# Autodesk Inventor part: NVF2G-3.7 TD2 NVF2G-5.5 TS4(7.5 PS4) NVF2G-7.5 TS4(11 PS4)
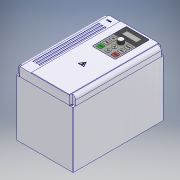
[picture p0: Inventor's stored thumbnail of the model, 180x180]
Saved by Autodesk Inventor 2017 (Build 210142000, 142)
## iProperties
Part Number: NVF2G-3.7 TD2 NVF2G-5.5 TS4(7.5 PS4) NVF2G-7.5 TS4(11 PS4)
Material: Типовые
Document SubType Name: Modeling
Designer: RSagdiev
Density: 1 g/cm^3
Appearance: По умолчанию
Mass: 6791.15 g
Surface Area: 3918.25 cm^2
Volume: 6791.15 cm^3
Author: RSagdiev
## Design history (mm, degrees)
sketch "Эскиз1"
  geometry: L1 (0, 0)-(44.679, 0) reference; L2 (0, 0)-(0, 56.035) reference; L3 (0, 0)-(247, 0); L4 (247, 0)-(247, 153.6); L5 (247, 153.6)-(0, 153.6); L6 (0, 153.6)-(0, 0)
  constraints: 12 end point, 3 horizontal, 2 parallel, 2 vertical, 1 perpendicular
  dimensions: "d0" = 247 distance of L5.end L4.end; "d1" = 153.6 distance of L4.end L3.end
extrude "Выдавливание1" new body sketch "Эскиз1" stored distance "d2" = 155; taper "d3" = 0 deg
sketch "Эскиз2"
  geometry: L1 (0, 0)-(0, 247) reference; L2 (155, 0)-(155, 247) reference; L3 (0, 247)-(10, 247); L4 (155, 247)-(155, 240); L5 (155, 0)-(145, 0); L6 (0, 0)-(0, 7); L7 (0, 247)-(155, 247) reference; L8 (0, 247)-(10, 247); L9 (10, 247)-(10, 240); L10 (10, 240)-(0, 240); L11 (0, 240)-(0, 247); L12 (155, 247)-(145, 247); L13 (145, 247)-(145, 240); L14 (145, 240)-(155, 240); L15 (155, 240)-(155, 247); L16 (0, 0)-(155, 0) reference; L17 (0, 0)-(10, 0); L18 (10, 0)-(10, 7); L19 (10, 7)-(0, 7); L20 (0, 7)-(0, 0); L21 (155, 0)-(145, 0); L22 (145, 0)-(145, 7); L23 (145, 7)-(155, 7); L24 (155, 7)-(155, 0); L25 (10, 247)-(145, 247); L26 (0, 240)-(0, 247); L27 (145, 247)-(155, 247); L28 (155, 240)-(155, 7); L29 (145, 0)-(10, 0); L30 (155, 7)-(155, 0); L31 (10, 0)-(0, 0); L32 (0, 7)-(0, 240); 1 further point
  constraints: 56 end point, 26 parallel, 13 perpendicular, 7 horizontal
  dimensions: "d4" = 10 distance of L9.end L10.end; "d5" = 7 distance of L3.end L9.end; "d6" = 10 distance of L4.end L13.end; "d7" = 7 distance of L13.end L12.end; "d8" = 10 distance of L6.end L18.end; "d9" = 7 distance of L18.end L17.end; "d10" = 10 distance of L22.end L23.end; "d11" = 7 distance of L5.end L22.end
extrude "Выдавливание2" new body sketch "Эскиз2" distance "d12" = 24; taper "d13" = 0 deg
chamfer "Фаска1" distance "d14" = 4; stored, may be unused: second distance "d15" = 2, angle "d16" = 45 deg
sketch "Эскиз3"
  geometry: L1 (10, 243)-(41.5, 243); L2 (10, 243)-(10, 240); L3 (10, 240)-(0, 240); L4 (0, 240)-(0, 7); L5 (0, 7)-(10, 7); L6 (10, 7)-(10, 0); L7 (10, 0)-(41.5, 0); L8 (145, 0)-(145, 7); L9 (145, 7)-(145, 7); L10 (145, 7)-(145, 240); L11 (145, 240)-(145, 240); L12 (145, 240)-(145, 243); L13 (10, 243)-(145, 243) reference; L14 (41.5, 243)-(41.5, 0); L15 (0, 0)-(155, 0) reference; L16 (41.5, 243)-(145, 243); L17 (41.5, 0)-(145, 0); L18 (145, 240)-(145, 243); 1 further point
  constraints: 22 end point, 2 perpendicular, 2 point on line, 1 collinear
  dimensions: "d19" = 103.5 distance between parallel lines of L14 L10
extrude "Выдавливание3" new body sketch "Эскиз3" distance "d17" = 2; taper "d18" = 0 deg
sketch "Эскиз4"
  geometry: L1 (123, 238)-(64, 238); L2 (62, 236)-(62, 147); L3 (64, 145)-(123, 145); L4 (125, 147)-(125, 236); L5 (10, 243)-(145, 243) reference; A1 r 2 centre (64, 236) between (64, 238) and (62, 236); A2 r 2 centre (123, 236) between (125, 236) and (123, 238); A3 r 2 centre (123, 147) between (123, 145) and (125, 147); A4 r 2 centre (64, 147) between (62, 147) and (64, 145); 7 further points; 1 other entity
  constraints: 8 end point, 8 point on circle, 8 tangent, 6 point on line, 4 centre point, 3 equal radius, 2 parallel, 1 horizontal, 1 perpendicular, 1 other
  dimensions: "d20" = 63 distance of point (125, 145) point (62, 145); "d21" = 93 distance of point (62, 145) point (62, 238); "d22" = 20 dimension on L4; "d23" = 5 distance between parallel lines of L5 L1; "d24" = 2 radius of A1
extrude "Выдавливание4" cut sketch "Эскиз4" distance "d25" = 0.6; taper "d26" = 0 deg
sketch "Эскиз5"
  geometry: L1 (0, 247)-(155, 247) reference; L2 (0, 0)-(0, 247) reference; L3 (155, 247)-(155, 0) reference; L4 (0, 0)-(155, 0) reference; C1 r 2.5 at (7.5, 243.5); C2 r 2.5 at (147.5, 243.5); C3 r 2.5 at (7.5, 3.5); C4 r 2.5 at (147.5, 3.5); 1 further point
  constraints: 4 centre point
  dimensions: "d27" = 5 diameter of C1; "d28" = 3.5 distance from line of C1.centre L1; "d29" = 7.5 distance from line of C1.centre L2; "d30" = 5 diameter of C2; "d31" = 3.5 distance from line of C2.centre L1; "d32" = 7.5 distance from line of C2.centre L3; "d33" = 5 diameter of C3; "d34" = 3.5 distance from line of L4 C3.centre; "d35" = 7.5 distance from line of C3.centre L2; "d36" = 5 diameter of C4; "d37" = 7.5 distance from line of C4.centre L3; "d38" = 3.5 distance from line of C4.centre L4
extrude "Выдавливание5" cut sketch "Эскиз5" stored distance "d39" = 0.6; taper "d40" = 0 deg
sketch "Эскиз6"
  geometry: L1 (62, 147)-(62, 203); L2 (123, 145)-(64, 145); L3 (125, 236)-(125, 203); L4 (64, 238)-(123, 238); L5 (62, 147)-(62, 236) reference; L6 (62, 203)-(125, 203); L7 (125, 236)-(125, 147) reference; L8 (62, 203)-(62, 236); L9 (125, 203)-(125, 147); L10 (75.5, 214)-(111.5, 214); L11 (113.5, 216)-(113.5, 226); L12 (111.5, 228)-(75.5, 228); L13 (73.5, 226)-(73.5, 216); L14 (73.5, 214)-(113.5, 228); L15 (113.5, 214)-(73.5, 228); L16 (93.5, 191.5)-(93.5, 156.857); L17 (85.25, 191.5)-(85.25, 156.857); L18 (101.75, 156.857)-(101.75, 191.5); L19 (79, 198)-(68, 198); L20 (67, 197)-(67, 186); L21 (68, 185)-(79, 185); L22 (80, 186)-(80, 197); L23 (80, 198)-(67, 185); L24 (67, 198)-(80, 185); L25 (113.5, 216)-(113.5, 217.5); L26 (73.5, 191.5)-(75.409, 191.5); L27 (26.654, 174.179)-(72.729, 174.179); L28 (26.654, 156.857)-(71.963, 156.857); L29 (120, 186)-(120, 197); L30 (108, 185)-(119, 185); L31 (120, 198)-(107, 185); L32 (107, 198)-(120, 185); L33 (107, 197)-(107, 186); L34 (119, 198)-(108, 198); L35 (120, 168.679)-(120, 179.679); L36 (108, 167.679)-(119, 167.679); L37 (120, 180.679)-(107, 167.679); L38 (107, 180.679)-(120, 167.679); L39 (107, 179.679)-(107, 168.679); L40 (119, 180.679)-(108, 180.679); L41 (120, 151.357)-(120, 162.357); L42 (108, 150.357)-(119, 150.357); L43 (120, 163.357)-(107, 150.357); L44 (107, 163.357)-(120, 150.357); L45 (107, 162.357)-(107, 151.357); L46 (119, 163.357)-(108, 163.357); L47 (80, 151.357)-(80, 162.357); L48 (68, 150.357)-(79, 150.357); L49 (80, 163.357)-(67, 150.357); L50 (67, 163.357)-(80, 150.357); L51 (67, 162.357)-(67, 151.357); L52 (79, 163.357)-(68, 163.357); L53 (80, 168.679)-(80, 179.679); L54 (68, 167.679)-(79, 167.679); L55 (80, 180.679)-(67, 167.679); L56 (67, 180.679)-(80, 167.679); L57 (67, 179.679)-(67, 168.679); L58 (79, 180.679)-(68, 180.679); L59 (123, 145)-(64, 145) reference; L60 (125, 236)-(125, 147) reference; L61 (73.5, 191.5)-(73.5, 91.5); C1 r 6.5 at (93.5, 191.5); C2 r 6.5 at (93.5, 156.857); C3 r 6.5 at (93.5, 174.179); A1 r 2 centre (75.5, 226) between (75.5, 228) and (73.5, 226); A2 r 2 centre (111.5, 226) between (113.5, 226) and (111.5, 228); A3 r 2 centre (111.5, 216) between (111.5, 214) and (113.5, 216); A4 r 2 centre (75.5, 216) between (73.5, 216) and (75.5, 214); A5 r 8.25 centre (93.5, 191.5) between (101.75, 191.5) and (85.25, 191.5); A6 r 8.25 centre (93.5, 156.857) between (85.25, 156.857) and (101.75, 156.857); A7 r 1 centre (79, 197) between (80, 197) and (79, 198); A8 r 1 centre (79, 186) between (79, 185) and (80, 186); A9 r 1 centre (68, 186) between (67, 186) and (68, 185); A10 r 1 centre (68, 197) between (68, 198) and (67, 197); A11 r 1 centre (119, 186) between (119, 185) and (120, 186); A12 r 1 centre (119, 197) between (120, 197) and (119, 198); A13 r 1 centre (108, 197) between (108, 198) and (107, 197); A14 r 1 centre (108, 186) between (107, 186) and (108, 185); A15 r 1 centre (119, 168.679) between (119, 167.679) and (120, 168.679); A16 r 1 centre (119, 179.679) between (120, 179.679) and (119, 180.679); A17 r 1 centre (108, 179.679) between (108, 180.679) and (107, 179.679); A18 r 1 centre (108, 168.679) between (107, 168.679) and (108, 167.679); A19 r 1 centre (119, 151.357) between (119, 150.357) and (120, 151.357); A20 r 1 centre (119, 162.357) between (120, 162.357) and (119, 163.357); A21 r 1 centre (108, 162.357) between (108, 163.357) and (107, 162.357); A22 r 1 centre (108, 151.357) between (107, 151.357) and (108, 150.357); A23 r 1 centre (79, 151.357) between (79, 150.357) and (80, 151.357); A24 r 1 centre (79, 162.357) between (80, 162.357) and (79, 163.357); A25 r 1 centre (68, 162.357) between (68, 163.357) and (67, 162.357); A26 r 1 centre (68, 151.357) between (67, 151.357) and (68, 150.357); A27 r 1 centre (79, 168.679) between (79, 167.679) and (80, 168.679); A28 r 1 centre (79, 179.679) between (80, 179.679) and (79, 180.679); A29 r 1 centre (68, 179.679) between (68, 180.679) and (67, 179.679); A30 r 1 centre (68, 168.679) between (67, 168.679) and (68, 167.679); A31 r 2 centre (64, 236) between (64, 238) and (62, 236) reference; A32 r 2 centre (123, 236) between (125, 236) and (123, 238) reference; A33 r 2 centre (123, 147) between (123, 145) and (125, 147) reference; A34 r 2 centre (64, 147) between (62, 147) and (64, 145) reference; 15 further points
  constraints: 112 end point, 70 point on line, 60 point on circle, 60 tangent, 33 centre point, 22 midpoint, 21 equal radius, 15 parallel, 11 horizontal, 7 perpendicular, 3 coincident, 3 vertical
  dimensions: "d43" = 35 distance between parallel lines of L4 L6; "d44" = 40 distance of L15.end L14.end; "d45" = 14 distance of L14.end L15.start; "d46" = 10 distance between parallel lines of L4 L12; "d47" = 2 radius of A1; "d48" = 11.5 distance between parallel lines of L8 L13; "d49" = 16.5 diameter of A6; "d50" = 31.5 distance between parallel lines of L1 L16; "d51" = 11.5 distance from line of L6 L16.start; "d52" = 11.85714 distance from line of L2 L16.end; "d53" = 13 diameter of C1; "d54" = 13 diameter of C2; "d55" = 13 diameter of C3; "d56" = 13 distance of L24.end L23.end; "d57" = 13 distance of L23.end L24.start; "d58" = 1 radius of A7 (derived); "d59" = 11.5 distance from line of L6 L26.start; "d60" = 11.5 distance from line of L5 L26.start; "d61" = 13 distance of L32.end L31.end; "d62" = 13 distance of L31.end L32.start; "d63" = 1 radius of A12 (derived); "d64" = 13 distance of L38.end L37.end; "d65" = 13 distance of L37.end L38.start; "d66" = 1 radius of A16 (derived); "d67" = 13 distance of L44.end L43.end; "d68" = 13 distance of L43.end L44.start; "d69" = 1 radius of A20 (derived); "d70" = 13 distance of L50.end L49.end; "d71" = 13 distance of L49.end L50.start; "d72" = 1 radius of A24 (derived); "d73" = 13 distance of L56.end L55.end; "d74" = 13 distance of L55.end L56.start; "d75" = 1 radius of A28 (derived)
extrude "Выдавливание6" new body sketch "Эскиз6" distance "d76" = 0.3; taper "d77" = 0 deg
extrude "Выдавливание7" new body sketch "Эскиз6" distance "d78" = 0.6; taper "d79" = 0 deg
sketch "Эскиз7"
  geometry: L1 (62, 203)-(125, 203) reference; L2 (125, 236)-(125, 147) reference; L3 (62, 203)-(125, 203); L4 (125, 203)-(125, 203.1); L5 (125, 203.1)-(62, 203.1); L6 (62, 203.1)-(62, 203); 1 further point
  constraints: 8 end point, 2 parallel, 1 horizontal, 1 perpendicular, 1 point on line
  dimensions: "d80" = 0.1 distance of L4.end L3.end
extrude "Выдавливание8" cut sketch "Эскиз7" distance "d81" = 0.3; taper "d82" = 0 deg
sketch "Эскиз8" dims "d91" = 10
  geometry: L1 (62, 203.1)-(125, 203.1) reference; L2 (62, 147)-(62, 236) reference; C1 r 1 at (70, 208.1); C2 r 1 at (77.75, 208.1); C3 r 1 at (85.5, 208.1); C4 r 1 at (93.25, 208.1); C5 r 1 at (101, 208.1); C6 r 1 at (108.75, 208.1); C7 r 1 at (116.5, 208.1); 1 further point
  constraints: 7 centre point, 1 horizontal, 12 other
  dimensions: "d83" = 2 diameter of C1; "d84" = 5 distance from line of C1.centre L1; "d85" = 8 distance from line of C1.centre L2; "d88" = 7.75 distance of C1.centre C2.centre
extrude "Выдавливание9" join sketch "Эскиз8" distance "d93" = 0.3; taper "d94" = 0 deg
sketch "Эскиз9"
  geometry: C1 r 6.5 at (0, 0) reference; C2 r 7.5 at (0, 0); 1 further point
  constraints: 1 centre point, 1 coincident
  dimensions: "d95" = 15 diameter of C2
extrude "Выдавливание10" join sketch "Эскиз9" distance "d96" = 9.4; taper "d97" = -3 deg
sketch "Эскиз10"
  geometry: L1 (0, 7.331)-(0.619, 6.259); L2 (0.619, 6.259)-(-0.619, 6.259); L3 (-0.619, 6.259)-(0, 7.331); 2 further points
  constraints: 6 end point, 7 other
sketch "Эскиз11"
  geometry: L1 (0, 7.917)-(0.884, 6.386); L2 (0.884, 6.386)-(-0.884, 6.386); L3 (-0.884, 6.386)-(0, 7.917); 2 further points
  constraints: 6 end point, 7 other
feature "Лофт1" sketch "Эскиз10", "Эскиз11" dims "d98" = 0, "d99" = 90 deg, "d100" = 0, "d101" = 90 deg
sketch "Эскиз12"
  geometry: L1 (70.126, 193.364)-(76.346, 193.364); L2 (76.346, 193.364)-(76.346, 189.864); L3 (76.346, 189.864)-(70.126, 189.864); L4 (70.126, 189.864)-(70.126, 193.364); L5 (69.176, 176.265)-(78.031, 176.265); L6 (78.031, 176.265)-(78.031, 172.635); L7 (78.031, 172.635)-(69.176, 172.635); L8 (69.176, 172.635)-(69.176, 176.265); L9 (68.82, 158.929)-(78.177, 158.929); L10 (78.177, 158.929)-(78.177, 155.355); L11 (78.177, 155.355)-(68.82, 155.355); L12 (68.82, 155.355)-(68.82, 158.929); L13 (107.649, 158.929)-(119.201, 158.929); L14 (119.201, 158.929)-(119.201, 155.281); L15 (119.201, 155.281)-(107.649, 155.281); L16 (107.649, 155.281)-(107.649, 158.929); L17 (109.43, 176.146)-(117.624, 176.146); L18 (117.624, 176.146)-(117.624, 172.522); L19 (117.624, 172.522)-(109.43, 172.522); L20 (109.43, 172.522)-(109.43, 176.146); L21 (107.53, 193.483)-(120.58, 193.483); L22 (120.58, 193.483)-(120.58, 189.858); L23 (120.58, 189.858)-(107.53, 189.858); L24 (107.53, 189.858)-(107.53, 193.483); 1 further point
  constraints: 12 other
feature "Рельеф1" dims "d105" = 0.1, "d106" = 0
feature "Рельеф2" dims "d107" = 0.1, "d108" = 0
feature "Рельеф3" dims "d109" = 0.1, "d110" = 0
feature "Рельеф4" dims "d111" = 0.1, "d112" = 0
feature "Рельеф5" dims "d113" = 0.1, "d114" = 0
feature "Рельеф6" dims "d115" = 0.1, "d116" = 0
sketch "Эскиз13"
  geometry: L1 (-3.144, -2.347)-(-0.04, 3.728); L2 (-0.04, 3.728)-(3.298, -2.347); L3 (3.298, -2.347)-(2.096, -2.347); L4 (2.096, -2.347)-(-0.04, 1.541); L5 (-0.04, 1.541)-(-2.027, -2.347); L6 (-2.027, -2.347)-(-3.144, -2.347); L7 (-9.387, -8.657)-(8.031, -8.657); L8 (-3.144, -14.967)-(-0.04, -21.041); L9 (-0.04, -21.041)-(3.298, -14.967); L10 (3.298, -14.967)-(2.096, -14.967); L11 (2.096, -14.967)-(-0.04, -18.855); L12 (-0.04, -18.855)-(-2.027, -14.967); L13 (-2.027, -14.967)-(-3.144, -14.967); 1 further point
  constraints: 26 end point, 6 symmetric about line, 2 horizontal, 2 parallel, 2 point on line, 1 collinear
feature "Рельеф7" dims "d117" = 0.1, "d118" = 0
feature "Рельеф8" dims "d119" = 0.1, "d120" = 0
sketch "Эскиз14"
  geometry: L1 (91.347, 99.459)-(99.644, 85.088); L2 (99.644, 85.088)-(83.05, 85.088); L3 (83.05, 85.088)-(91.347, 99.459); L4 (98.216, 85.912)-(91.347, 97.81); L5 (91.347, 97.81)-(84.478, 85.912); L6 (84.478, 85.912)-(98.216, 85.912); L7 (90.52, 94.143)-(89.579, 90.333); L8 (89.579, 90.333)-(92.001, 90.503); L9 (92.001, 90.503)-(90.959, 88.187); L10 (90.959, 88.187)-(90.01, 88.614); L11 (90.01, 88.614)-(90.166, 86.383); L12 (90.166, 86.383)-(92.637, 87.433); L13 (92.637, 87.433)-(91.956, 87.739); L14 (91.956, 87.739)-(93.885, 91.375); L15 (93.885, 91.375)-(90.73, 91.192); L16 (90.73, 91.192)-(92.296, 94.143); L17 (92.296, 94.143)-(90.52, 94.143); 2 further points
  constraints: 34 end point, 2 perpendicular, 2 point on line, 1 parallel, 9 other
extrude "Выдавливание11" cut sketch "Эскиз14" distance "d121" = 0.1; taper "d122" = 0 deg
extrude "Выдавливание12" join sketch "Эскиз14" distance "d123" = 0.05; taper "d124" = 0 deg
sketch "Эскиз15"
  geometry: L1 (63.713, 212.502)-(88.407, 212.502); L2 (88.407, 212.502)-(88.407, 209.614); L3 (88.407, 209.614)-(63.713, 209.614); L4 (63.713, 209.614)-(63.713, 212.502); L5 (89.448, 212.055)-(120.389, 212.055); L6 (120.389, 212.055)-(120.389, 207.965); L7 (120.389, 207.965)-(89.448, 207.965); L8 (89.448, 207.965)-(89.448, 212.055); 1 further point
  constraints: 4 other
feature "Рельеф9" sketch "Эскиз15" dims "d125" = 0.1, "d126" = 0
sketch "Эскиз16" dims "d133" = 10, "d140" = 10
  geometry: L1 (-46.348, 218.18)-(-46.348, 196.213); L2 (-47.848, 218.18)-(-47.848, 196.213); L3 (-44.848, 196.213)-(-44.848, 218.18); L4 (0, 229)-(4, 229) reference; L5 (-40.348, 218.18)-(-40.348, 196.213); L6 (-41.848, 218.18)-(-41.848, 196.213); L7 (-38.848, 196.213)-(-38.848, 218.18); L8 (-34.348, 218.18)-(-34.348, 196.213); L9 (-35.848, 218.18)-(-35.848, 196.213); L10 (-32.848, 196.213)-(-32.848, 218.18); L11 (-28.348, 218.18)-(-28.348, 196.213); L12 (-29.848, 218.18)-(-29.848, 196.213); L13 (-26.848, 196.213)-(-26.848, 218.18); L14 (-22.348, 218.18)-(-22.348, 196.213); L15 (-23.848, 218.18)-(-23.848, 196.213); L16 (-20.848, 196.213)-(-20.848, 218.18); L17 (-47.848, 188.18)-(-47.848, 166.213); L18 (-46.348, 188.18)-(-46.348, 166.213); L19 (-44.848, 166.213)-(-44.848, 188.18); L20 (-41.848, 188.18)-(-41.848, 166.213); L21 (-38.848, 166.213)-(-38.848, 188.18); L22 (-35.848, 188.18)-(-35.848, 166.213); L23 (-34.348, 188.18)-(-34.348, 166.213); L24 (-32.848, 166.213)-(-32.848, 188.18); L25 (-29.848, 188.18)-(-29.848, 166.213); L26 (-28.348, 188.18)-(-28.348, 166.213); L27 (-26.848, 166.213)-(-26.848, 188.18); L28 (-23.848, 188.18)-(-23.848, 166.213); L29 (-22.348, 188.18)-(-22.348, 166.213); L30 (-20.848, 166.213)-(-20.848, 188.18); L31 (-40.348, 188.18)-(-40.348, 166.213); L32 (-47.848, 158.18)-(-47.848, 136.213); L33 (-46.348, 158.18)-(-46.348, 136.213); L34 (-44.848, 136.213)-(-44.848, 158.18); L35 (-41.848, 158.18)-(-41.848, 136.213); L36 (-38.848, 136.213)-(-38.848, 158.18); L37 (-35.848, 158.18)-(-35.848, 136.213); L38 (-34.348, 158.18)-(-34.348, 136.213); L39 (-32.848, 136.213)-(-32.848, 158.18); L40 (-29.848, 158.18)-(-29.848, 136.213); L41 (-28.348, 158.18)-(-28.348, 136.213); L42 (-26.848, 136.213)-(-26.848, 158.18); L43 (-23.848, 158.18)-(-23.848, 136.213); L44 (-22.348, 158.18)-(-22.348, 136.213); L45 (-20.848, 136.213)-(-20.848, 158.18); L46 (-40.348, 158.18)-(-40.348, 136.213); L47 (-47.848, 128.18)-(-47.848, 106.213); L48 (-46.348, 128.18)-(-46.348, 106.213); L49 (-44.848, 106.213)-(-44.848, 128.18); L50 (-41.848, 128.18)-(-41.848, 106.213); L51 (-38.848, 106.213)-(-38.848, 128.18); L52 (-35.848, 128.18)-(-35.848, 106.213); L53 (-34.348, 128.18)-(-34.348, 106.213); L54 (-32.848, 106.213)-(-32.848, 128.18); L55 (-29.848, 128.18)-(-29.848, 106.213); L56 (-28.348, 128.18)-(-28.348, 106.213); L57 (-26.848, 106.213)-(-26.848, 128.18); L58 (-23.848, 128.18)-(-23.848, 106.213); L59 (-22.348, 128.18)-(-22.348, 106.213); L60 (-20.848, 106.213)-(-20.848, 128.18); L61 (-40.348, 128.18)-(-40.348, 106.213); A1 r 1.5 centre (-46.348, 218.18) between (-44.848, 218.18) and (-47.848, 218.18); A2 r 1.5 centre (-46.348, 196.213) between (-47.848, 196.213) and (-44.848, 196.213); A3 r 1.5 centre (-40.348, 218.18) between (-38.848, 218.18) and (-41.848, 218.18); A4 r 1.5 centre (-40.348, 196.213) between (-41.848, 196.213) and (-38.848, 196.213); A5 r 1.5 centre (-34.348, 218.18) between (-32.848, 218.18) and (-35.848, 218.18); A6 r 1.5 centre (-34.348, 196.213) between (-35.848, 196.213) and (-32.848, 196.213); A7 r 1.5 centre (-28.348, 218.18) between (-26.848, 218.18) and (-29.848, 218.18); A8 r 1.5 centre (-28.348, 196.213) between (-29.848, 196.213) and (-26.848, 196.213); A9 r 1.5 centre (-22.348, 218.18) between (-20.848, 218.18) and (-23.848, 218.18); A10 r 1.5 centre (-22.348, 196.213) between (-23.848, 196.213) and (-20.848, 196.213); A11 r 1.5 centre (-46.348, 166.213) between (-47.848, 166.213) and (-44.848, 166.213); A12 r 1.5 centre (-40.348, 188.18) between (-38.848, 188.18) and (-41.848, 188.18); A13 r 1.5 centre (-46.348, 188.18) between (-44.848, 188.18) and (-47.848, 188.18); A14 r 1.5 centre (-34.348, 188.18) between (-32.848, 188.18) and (-35.848, 188.18); A15 r 1.5 centre (-22.348, 188.18) between (-20.848, 188.18) and (-23.848, 188.18); A16 r 1.5 centre (-28.348, 188.18) between (-26.848, 188.18) and (-29.848, 188.18); A17 r 1.5 centre (-40.348, 166.213) between (-41.848, 166.213) and (-38.848, 166.213); A18 r 1.5 centre (-34.348, 166.213) between (-35.848, 166.213) and (-32.848, 166.213); A19 r 1.5 centre (-28.348, 166.213) between (-29.848, 166.213) and (-26.848, 166.213); A20 r 1.5 centre (-22.348, 166.213) between (-23.848, 166.213) and (-20.848, 166.213); A21 r 1.5 centre (-46.348, 136.213) between (-47.848, 136.213) and (-44.848, 136.213); A22 r 1.5 centre (-40.348, 158.18) between (-38.848, 158.18) and (-41.848, 158.18); A23 r 1.5 centre (-46.348, 158.18) between (-44.848, 158.18) and (-47.848, 158.18); A24 r 1.5 centre (-34.348, 158.18) between (-32.848, 158.18) and (-35.848, 158.18); A25 r 1.5 centre (-22.348, 158.18) between (-20.848, 158.18) and (-23.848, 158.18); A26 r 1.5 centre (-28.348, 158.18) between (-26.848, 158.18) and (-29.848, 158.18); A27 r 1.5 centre (-40.348, 136.213) between (-41.848, 136.213) and (-38.848, 136.213); A28 r 1.5 centre (-34.348, 136.213) between (-35.848, 136.213) and (-32.848, 136.213); A29 r 1.5 centre (-28.348, 136.213) between (-29.848, 136.213) and (-26.848, 136.213); A30 r 1.5 centre (-22.348, 136.213) between (-23.848, 136.213) and (-20.848, 136.213); A31 r 1.5 centre (-46.348, 106.213) between (-47.848, 106.213) and (-44.848, 106.213); A32 r 1.5 centre (-40.348, 128.18) between (-38.848, 128.18) and (-41.848, 128.18); A33 r 1.5 centre (-46.348, 128.18) between (-44.848, 128.18) and (-47.848, 128.18); A34 r 1.5 centre (-34.348, 128.18) between (-32.848, 128.18) and (-35.848, 128.18); A35 r 1.5 centre (-22.348, 128.18) between (-20.848, 128.18) and (-23.848, 128.18); A36 r 1.5 centre (-28.348, 128.18) between (-26.848, 128.18) and (-29.848, 128.18); A37 r 1.5 centre (-40.348, 106.213) between (-41.848, 106.213) and (-38.848, 106.213); A38 r 1.5 centre (-34.348, 106.213) between (-35.848, 106.213) and (-32.848, 106.213); A39 r 1.5 centre (-28.348, 106.213) between (-29.848, 106.213) and (-26.848, 106.213); A40 r 1.5 centre (-22.348, 106.213) between (-23.848, 106.213) and (-20.848, 106.213); 22 further points
  constraints: 160 end point, 80 point on circle, 40 centre point, 4 tangent, 2 vertical, 1 collinear, 1 horizontal, 1 midpoint, 1 parallel, 227 other
  dimensions: "d127" = 3 diameter of A2; "d130" = 6 distance of L2.start L6.start; "d137" = 30 distance of L6.end L20.end
extrude "Выдавливание13" cut sketch "Эскиз16" distance "d142" = 18.55; taper "d143" = 0 deg
sketch "Эскиз17"
  geometry: L1 (17.427, 231.089)-(24.426, 231.089); L2 (24.426, 231.089)-(24.426, 283.919); L3 (24.426, 283.919)-(17.427, 283.919); L4 (17.427, 283.919)-(17.427, 231.089); 1 further point
  constraints: 2 other
feature "Рельеф10" sketch "Эскиз17" dims "d144" = 0.1, "d145" = 0
fillet "Сопряжение3" dims "d146" = 10
sketch "Эскиз19" dims "d156" = 10
  geometry: L1 (15, 210)-(19, 210); L2 (19, 210)-(19, 30); L3 (19, 30)-(15, 30); L4 (15, 30)-(15, 210); L5 (10, 7)-(10, 240) reference; L6 (10, 0)-(145, 0) reference; L7 (23, 210)-(27, 210); L8 (27, 210)-(27, 30); L9 (27, 30)-(23, 30); L10 (23, 30)-(23, 210); L11 (31, 210)-(35, 210); L12 (35, 210)-(35, 30); L13 (35, 30)-(31, 30); L14 (31, 30)-(31, 210); 1 further point
  constraints: 24 end point, 2 horizontal, 2 parallel, 1 collinear, 1 perpendicular, 15 other
  dimensions: "d147" = 4 distance of L2.end L3.end; "d148" = 180 distance of L1.end L2.end; "d149" = 5 distance between parallel lines of L5 L4; "d150" = 30 distance between parallel lines of L6 L3; "d153" = 8 distance of L1.start L7.start
extrude "Выдавливание14" cut sketch "Эскиз19" distance "d158" = 1; taper "d159" = 0 deg
fillet "Сопряжение4" dims "d160" = 2
node "Твердое тело1"
pattern_circular "Круговой массив1" dims angle "d103" = 360 deg
node "Твердое тело2"
node "Твердое тело3"
node "Твердое тело4"
node "Твердое тело5"
